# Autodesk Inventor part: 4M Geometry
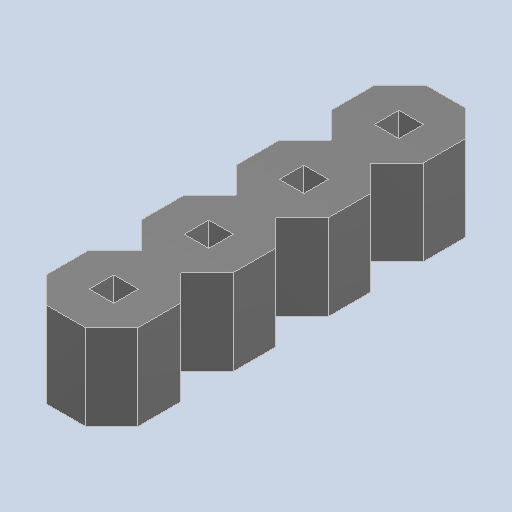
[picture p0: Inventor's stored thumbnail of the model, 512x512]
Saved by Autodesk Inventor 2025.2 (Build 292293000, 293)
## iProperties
Created: 2025-04
Part Number: 4M Geometry
Material: Generic
Description: PART-4M Geometry-DESC
Document SubType Name: Modeling
Designer: BennF
Density: 1 g/cm^3
Appearance: Default
Author: BennF
Revision Number: NONE
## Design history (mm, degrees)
feature "4"
body "Solid1"
